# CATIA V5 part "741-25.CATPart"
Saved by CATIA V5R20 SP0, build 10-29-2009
Part number: 741-25
Bounding box of the stored display mesh (mm): x -24 to 24.335, y -23.94 to 23.94, z -23 to 36
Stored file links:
  C:\Users\Utente\Desktop\IO LAVORO\3D X SITO CF\X SITO\741\741-25.CATPart
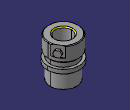
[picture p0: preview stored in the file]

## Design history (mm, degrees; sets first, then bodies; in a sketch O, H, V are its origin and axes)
Set1
  DatumSurface1 to DatumSurface42 "741-25"
Body1 (main body)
